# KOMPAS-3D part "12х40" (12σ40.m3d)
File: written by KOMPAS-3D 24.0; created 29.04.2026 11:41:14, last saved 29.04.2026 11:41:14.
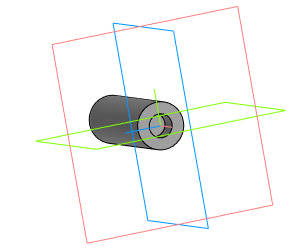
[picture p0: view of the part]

Document properties: Автор: USG_411; Полное имя файла: C:\Users\USG_411\Desktop\ИА-2904_411-12\12х40.m3d

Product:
- Part/product: 12х40
    Масса: 0.032874

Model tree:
1. Эскиз:1
2. Элемент выдавливания:1
     Расстояние 2 = 40
3. Эскиз:2  (with: Грань.Элемент выдавливания:1)
4. Элемент выдавливания:2
     Расстояние 2 = 6
5. Эскиз:3  (with: Грань.Элемент выдавливания:1)
6. Элемент выдавливания:3
     Расстояние 2 = 6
